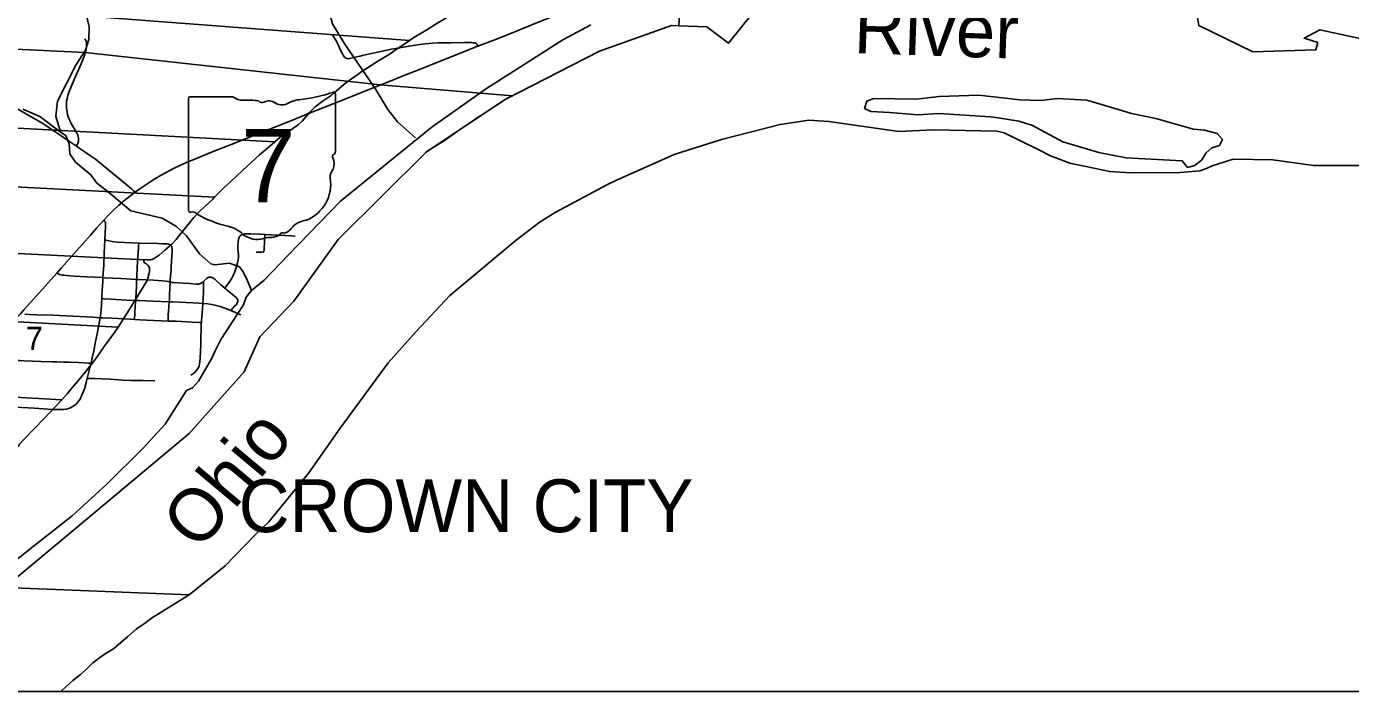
# Model space of a CAD drawing. Extents: x 0 to 34, y 0 to 22.
# Drawn here: x 27.11 to 29.485, y 14.1 to 15.294 of the extents above; entities that cross this region are included whole.
import ezdxf

# ---------------------------------------------------------------- set-up
doc = ezdxf.new("R2010")
doc.units = 0
for name, color, linetype in [('GM_X_City_Street', 7, 'Continuous'), ('GM_X_Corporation', 7, 'Continuous'), ('GM_X_Corporation_Text', 7, 'Continuous'), ('GM_X_County_Text', 7, 'Continuous'), ('GM_X_Major_River', 7, 'Continuous'), ('GM_X_Major_River_Text', 7, 'Continuous'), ('GM_X_Minor_River', 7, 'Continuous'), ('GM_X_Section', 7, 'Continuous'), ('GM_X_Section_Text', 7, 'Continuous'), ('GM_X_State_Location', 7, 'Continuous'), ('GM_X_State_Route', 7, 'Continuous'), ('GM_X_State_Shield', 7, 'Continuous'), ('GM_X_Township_Road', 7, 'Continuous'), ('SH_Cut_Line', 7, 'Continuous'), ('SH_Data', 7, 'Continuous')]:
    doc.layers.add(name, color=color, linetype=linetype)

msp = doc.modelspace()

# ---------------------------------------------------------------- linework, layer by layer
at = {"layer": 'GM_X_City_Street'}
for points in [[(27.0773, 14.6109), (27.1124, 14.609), (27.1242, 14.6084), (27.1478, 14.6069), (27.1583, 14.6064), (27.17, 14.6062), (27.1768, 14.6064), (27.181, 14.607), (27.1852, 14.6079), (27.1885, 14.6092), (27.1918, 14.6108), (27.1953, 14.6132), (27.1985, 14.6159), (27.201, 14.6186), (27.204, 14.6224), (27.2063, 14.626), (27.2085, 14.6304), (27.2114, 14.6372), (27.2134, 14.643), (27.2164, 14.6543), (27.2184, 14.6619), (27.2233, 14.6808), (27.2254, 14.6892), (27.2277, 14.6987), (27.2308, 14.7138), (27.2331, 14.7259), (27.2336, 14.7283), (27.2347, 14.7337), (27.2364, 14.7422), (27.239, 14.7549), (27.2412, 14.7671), (27.2417, 14.7707), (27.2424, 14.775), (27.2433, 14.7843), (27.2445, 14.8052), (27.2448, 14.8109), (27.2464, 14.8357), (27.2468, 14.8429), (27.2481, 14.8654), (27.2489, 14.8865), (27.25, 14.9104), (27.2515, 14.9348), (27.2516, 14.9409), (27.2511, 14.9422), (27.2503, 14.9434), (27.2475, 14.9453)], [(27.4942, 14.919), (27.4959, 14.9198), (27.4982, 14.9206), (27.5013, 14.9212), (27.5056, 14.9215), (27.5124, 14.9214), (27.528, 14.9207), (27.5372, 14.9203), (27.5479, 14.9198), (27.574, 14.9183), (27.5851, 14.9177), (27.5915, 14.9174)], [(27.5355, 14.889), (27.5359, 14.8939), (27.5367, 14.9081), (27.5371, 14.9173), (27.5372, 14.9203)], [(27.25, 14.9104), (27.2575, 14.9088), (27.2602, 14.9083), (27.2664, 14.9072), (27.2725, 14.9065), (27.2856, 14.906), (27.311, 14.9049), (27.3122, 14.9048), (27.3451, 14.904), (27.354, 14.9037), (27.3618, 14.9032), (27.3641, 14.9028), (27.3659, 14.9022), (27.367, 14.9016), (27.3679, 14.901), (27.3692, 14.8999), (27.3703, 14.8986)], [(27.3033, 14.7679), (27.3039, 14.7797), (27.3047, 14.7914), (27.3052, 14.7977), (27.3057, 14.8018), (27.306, 14.8066), (27.3065, 14.8157), (27.3068, 14.8268), (27.3072, 14.8396), (27.3074, 14.8441), (27.3083, 14.8609), (27.3096, 14.88), (27.3105, 14.8961), (27.3107, 14.8998), (27.311, 14.9049)], [(27.3636, 14.7649), (27.3638, 14.7687), (27.3639, 14.7718), (27.364, 14.7761), (27.3644, 14.7829), (27.365, 14.7909), (27.3656, 14.7994), (27.366, 14.8039), (27.3664, 14.8113), (27.367, 14.8243), (27.3673, 14.8347), (27.3675, 14.8391), (27.3689, 14.8571), (27.3694, 14.8626), (27.3703, 14.8805), (27.3708, 14.8898), (27.3708, 14.8939), (27.3706, 14.8971), (27.3703, 14.8986)], [(27.4653, 14.8238), (27.4705, 14.8305), (27.4752, 14.8371), (27.4781, 14.8418), (27.4806, 14.8468), (27.4832, 14.8532), (27.4857, 14.8608), (27.4881, 14.8692), (27.4893, 14.8747), (27.4898, 14.8796), (27.4898, 14.884), (27.4889, 14.8951), (27.4889, 14.8995), (27.4894, 14.9063), (27.4902, 14.9118), (27.4906, 14.9136), (27.4913, 14.9153), (27.4921, 14.9169), (27.4932, 14.9181), (27.4942, 14.919)], [(27.5214, 14.8886), (27.5278, 14.8887), (27.5324, 14.8888), (27.5355, 14.889)], [(27.1638, 14.8507), (27.1691, 14.8487), (27.1736, 14.8475), (27.1766, 14.847), (27.1815, 14.8465), (27.1951, 14.8456), (27.2174, 14.8444), (27.2468, 14.8429), (27.2503, 14.8427), (27.2788, 14.8414), (27.3072, 14.8396), (27.3104, 14.8394), (27.3377, 14.838), (27.3532, 14.8371), (27.3593, 14.8365), (27.3632, 14.8359), (27.3656, 14.8352), (27.3673, 14.8347), (27.3705, 14.8341), (27.3725, 14.8338), (27.3911, 14.8328), (27.4029, 14.832), (27.4142, 14.831), (27.4158, 14.8309), (27.417, 14.831), (27.4183, 14.8312), (27.4194, 14.8314), (27.4207, 14.8317), (27.4217, 14.8321), (27.4228, 14.8326), (27.4238, 14.8332), (27.4248, 14.8339), (27.4257, 14.8347), (27.4269, 14.836), (27.4325, 14.8412), (27.4346, 14.8426), (27.4358, 14.8432), (27.437, 14.8435), (27.4384, 14.8437), (27.4394, 14.8437), (27.4402, 14.8436), (27.4412, 14.8435), (27.4423, 14.8431), (27.444, 14.8424), (27.4453, 14.8416), (27.4462, 14.8409), (27.4481, 14.8394), (27.4495, 14.838), (27.4576, 14.8303), (27.4653, 14.8238), (27.4694, 14.8203), (27.4825, 14.8099), (27.4857, 14.8072), (27.4867, 14.8061), (27.4877, 14.8044), (27.4881, 14.8035)], [(27.4046, 14.6677), (27.408, 14.67), (27.4115, 14.6727), (27.4141, 14.6753), (27.4161, 14.6777), (27.4176, 14.6804), (27.4192, 14.6844), (27.4202, 14.688), (27.4209, 14.6923), (27.4214, 14.6991), (27.4217, 14.7103), (27.4222, 14.7233), (27.4223, 14.7326), (27.4227, 14.7525), (27.4231, 14.7599), (27.4234, 14.7623), (27.4238, 14.7667), (27.4243, 14.7723), (27.4259, 14.7952), (27.4259, 14.7962), (27.427, 14.8156), (27.4274, 14.8239), (27.4272, 14.8313), (27.4269, 14.836)], [(27.2445, 14.8052), (27.2491, 14.8049), (27.2609, 14.8041), (27.2702, 14.8035), (27.2893, 14.8025), (27.3057, 14.8018), (27.3123, 14.8016), (27.3365, 14.8006), (27.3656, 14.7994), (27.3724, 14.7991), (27.3842, 14.7985), (27.3959, 14.7979), (27.409, 14.7973), (27.4189, 14.7967), (27.4259, 14.7962), (27.4349, 14.7955), (27.4417, 14.7947), (27.4477, 14.7934), (27.4572, 14.7907), (27.4684, 14.787), (27.4764, 14.7839), (27.4845, 14.7805), (27.4943, 14.7763)], [(27.4764, 14.7839), (27.4794, 14.7873), (27.4836, 14.7919), (27.4861, 14.7948), (27.4876, 14.7969), (27.4882, 14.7986), (27.4886, 14.8), (27.4886, 14.8011), (27.4885, 14.8023), (27.4881, 14.8035)], [(27.1069, 14.7772), (27.1149, 14.7767), (27.1279, 14.7761), (27.1571, 14.7752), (27.193, 14.7737), (27.2172, 14.7726), (27.2289, 14.7718), (27.2417, 14.7707)], [(27.2417, 14.7707), (27.2463, 14.7705), (27.263, 14.7698), (27.2953, 14.7682), (27.3033, 14.7679), (27.3127, 14.7673), (27.3258, 14.7665), (27.3518, 14.7654), (27.3636, 14.7649), (27.3779, 14.7645), (27.3879, 14.764), (27.4071, 14.7628), (27.4202, 14.7624), (27.4234, 14.7623)], [(27.0272, 14.6976), (27.0383, 14.6967), (27.0572, 14.6959), (27.0742, 14.6949), (27.0823, 14.6944), (27.0934, 14.694), (27.0978, 14.6939), (27.1052, 14.6935), (27.1356, 14.6924), (27.1548, 14.6916), (27.1641, 14.6915), (27.1765, 14.6913), (27.187, 14.6911), (27.2031, 14.6903), (27.2205, 14.6894), (27.2254, 14.6892)], [(27.2184, 14.6619), (27.2323, 14.6616), (27.2441, 14.661), (27.2596, 14.6604), (27.2744, 14.6595), (27.2824, 14.659), (27.2976, 14.6584), (27.3192, 14.6579), (27.3397, 14.6577)]]:
    msp.add_lwpolyline(points, dxfattribs=at)
at = {"layer": 'GM_X_Corporation'}
msp.add_lwpolyline([(26.9519, 15.2596), (27.2149, 15.247), (27.7442, 15.1889), (27.9818, 15.1692), (27.9753, 15.166), (27.9674, 15.162), (27.9605, 15.1574), (27.944, 15.1463), (27.9311, 15.1378), (27.9164, 15.1281), (27.9019, 15.1184), (27.8907, 15.1109), (27.8595, 15.089), (27.83, 15.0701), (27.8265, 15.0679), (27.6689, 14.9115), (27.5892, 14.8006), (27.528, 14.7368), (27.5003, 14.6738), (27.4012, 14.5633), (27.1862, 14.3829), (27.0716, 14.2873)], dxfattribs=at)
at = {"layer": 'GM_X_County_Text'}
for points in [[(27.0716, 14.2873), (27.1862, 14.3829), (27.4012, 14.5633), (27.5003, 14.6738), (27.528, 14.7368), (27.5892, 14.8006), (27.6689, 14.9115), (27.8265, 15.0679), (27.967, 15.1616), (28.1376, 15.2493), (28.2671, 15.2953), (28.2799, 15.2948), (28.2867, 15.4004), (28.3527, 16.4269), (28.3944, 17.0528), (28.4159, 17.3358), (28.4427, 17.7695)], [(28.4427, 17.7695), (28.4159, 17.3358), (28.3944, 17.0528), (28.3527, 16.4269), (28.2867, 15.4004), (28.2799, 15.2948), (28.3301, 15.293), (28.3692, 15.2637), (28.4182, 15.3245), (28.4801, 15.3522), (28.6571, 15.3822), (28.9104, 15.3867), (29.0987, 15.3975), (29.1238, 15.3963), (29.3286, 15.3596), (29.3112, 15.3354), (29.211, 15.3094), (29.213, 15.295), (29.3097, 15.2479), (29.423, 15.2518), (29.4264, 15.2648), (29.4018, 15.2725), (29.4304, 15.2876), (29.5713, 15.2568)]]:
    msp.add_lwpolyline(points, dxfattribs=at)
at = {"layer": 'GM_X_Major_River'}
msp.add_line((27.0305, 14.2886), (27.4015, 14.2737), dxfattribs=at)
for points in [[(28.1223, 15.2965), (28.072, 15.2695), (27.9348, 15.1821), (27.8373, 15.1133), (27.7587, 15.0496), (27.6729, 14.9801), (27.5796, 14.8836), (27.5361, 14.8381), (27.5131, 14.8198), (27.5037, 14.8077), (27.4988, 14.794), (27.458, 14.7318), (27.4478, 14.7105), (27.4414, 14.6973), (27.418, 14.6567), (27.4074, 14.6453), (27.3964, 14.64), (27.3587, 14.58), (27.3183, 14.5359), (27.2544, 14.4725), (27.1913, 14.4152), (27.1214, 14.3605), (27.0305, 14.2886)], [(29.0923, 15.1371), (29.071, 15.1437), (29.0123, 15.1611), (28.959, 15.164), (28.9303, 15.1606), (28.8917, 15.1617), (28.8183, 15.1703), (28.7472, 15.1679), (28.7067, 15.1633), (28.63, 15.1644), (28.6171, 15.1594), (28.6133, 15.1465), (28.6243, 15.1409), (28.6587, 15.1394), (28.709, 15.1349), (28.7468, 15.1376), (28.8391, 15.1313), (28.8528, 15.1294), (28.8902, 15.1234), (28.9148, 15.1158), (28.9689, 15.0867), (29.0336, 15.0674), (29.0828, 15.058)], [(29.0828, 15.058), (29.1833, 15.0526), (29.1928, 15.0405), (29.2057, 15.0443), (29.2185, 15.0542), (29.2265, 15.0667), (29.2367, 15.0758), (29.25, 15.08), (29.2556, 15.0907), (29.2461, 15.1013), (29.2234, 15.1077), (29.2033, 15.1092), (29.1358, 15.1284), (29.0923, 15.1371)], [(27.4015, 14.2737), (27.466, 14.3257), (27.52, 14.3815), (27.5446, 14.4043), (27.6159, 14.4924), (27.6722, 14.5728), (27.7583, 14.6901), (27.8086, 14.7463), (27.8694, 14.8108), (27.9884, 14.9103), (28.0311, 14.943), (28.0583, 14.9597), (28.1521, 15.0102), (28.1672, 15.0171), (28.2715, 15.0638), (28.3566, 15.0905), (28.4617, 15.1179), (28.5135, 15.1256), (28.5494, 15.1233), (28.675, 15.1049), (28.7363, 15.108), (28.8505, 15.1055), (28.8637, 15.1029), (28.925, 15.073), (28.947, 15.0613), (28.9818, 15.048), (29.0533, 15.033), (29.0911, 15.0311)], [(29.0911, 15.0311), (29.1795, 15.0317), (29.2151, 15.0345), (29.2269, 15.0386), (29.2371, 15.0436), (29.2746, 15.0554), (29.3459, 15.0544), (29.419, 15.0438), (29.5115, 15.044)], [(27.1711, 14.1), (27.1805, 14.109), (27.193, 14.1197), (27.2058, 14.13), (27.2171, 14.1399), (27.2288, 14.1517), (27.2408, 14.1605), (27.251, 14.1674), (27.2657, 14.1769), (27.2789, 14.188), (27.291, 14.1979), (27.3064, 14.212), (27.323, 14.2235), (27.3336, 14.2319), (27.4015, 14.2737)]]:
    msp.add_lwpolyline(points, dxfattribs=at)
at = {"layer": 'GM_X_Minor_River'}
for points in [[(27.1708, 15.1045), (27.1625, 15.1324), (27.1653, 15.1597), (27.1982, 15.2243), (27.2153, 15.2508), (27.2215, 15.2699), (27.2222, 15.2931), (27.2141, 15.326), (27.2073, 15.3604), (27.1796, 15.4095), (27.1705, 15.4333), (27.1577, 15.496), (27.1332, 15.5484), (27.123, 15.5719), (27.1185, 15.6005)], [(27.8078, 15.0936), (27.775, 15.1224), (27.7579, 15.1446), (27.7366, 15.1806), (27.6794, 15.2637), (27.6589, 15.2981), (27.6545, 15.3138), (27.5904, 15.4309), (27.545, 15.4779), (27.496, 15.5072), (27.4775, 15.5222), (27.4551, 15.556)], [(27.5131, 14.8198), (27.5045, 14.8413), (27.4973, 14.8548), (27.4915, 14.8619), (27.4739, 14.8685), (27.4474, 14.8655), (27.4406, 14.8673), (27.42, 14.8854), (27.3964, 14.9177), (27.3788, 14.9346), (27.3528, 14.9494), (27.2969, 14.9626), (27.2534, 14.9993), (27.236, 15.0124), (27.2251, 15.0272), (27.1978, 15.0501), (27.1873, 15.0652), (27.1864, 15.0831), (27.18, 15.0977), (27.1726, 15.1029), (27.1334, 15.1319), (27.1028, 15.1454)]]:
    msp.add_lwpolyline(points, dxfattribs=at)
at = {"layer": 'GM_X_Section'}
msp.add_lwpolyline([(27.1082, 16.21), (27.1198, 16.4014), (27.6098, 16.3785), (28.1612, 16.354), (28.1022, 15.4021), (28.0942, 15.3994), (28.073, 15.3933), (28.0541, 15.3891), (28.0393, 15.3864), (28.0147, 15.3799), (27.9901, 15.3708), (27.9704, 15.362), (27.9454, 15.3502), (27.9269, 15.3415), (27.9046, 15.3316), (27.8826, 15.3209), (27.8697, 15.3133), (27.8576, 15.3061), (27.8429, 15.297), (27.8281, 15.2875), (27.8077, 15.2753), (27.7994, 15.27), (27.7971, 15.2681), (27.0537, 15.3245)], dxfattribs=at)
for points in [[(27.0537, 15.3245), (27.7971, 15.2681), (27.7884, 15.2624), (27.7785, 15.2559), (27.771, 15.251), (27.7619, 15.2445), (27.743, 15.2331), (27.7146, 15.2152), (27.6987, 15.2038), (27.6828, 15.1924), (27.6624, 15.1753), (27.656, 15.1697), (27.6401, 15.159), (27.6276, 15.1491), (27.6174, 15.1393), (27.6042, 15.1237), (27.597, 15.1172), (27.5777, 15.1036), (27.5644, 15.0941), (27.5553, 15.0864), (27.0368, 15.114)], [(27.0368, 15.114), (27.5553, 15.0864), (27.5463, 15.0789), (27.5274, 15.0629), (27.4979, 15.0356), (27.4752, 15.0143), (27.4642, 15.0048), (27.447, 14.9872), (27.0298, 15.0085)], [(27.447, 14.9872), (27.4438, 14.9839), (27.4294, 14.9703), (27.4192, 14.9608), (27.4098, 14.9505), (27.3965, 14.9346), (27.3799, 14.9137), (27.378, 14.9114), (27.3701, 14.9027), (27.3576, 14.892), (27.3478, 14.8833), (27.3387, 14.8769), (27.3345, 14.8753), (27.3315, 14.8746), (27.3262, 14.8749), (27.3237, 14.8752), (27.3209, 14.8747), (27.022, 14.8897), (27.0298, 15.0085)], [(27.022, 14.8897), (27.3209, 14.8747), (27.3201, 14.872), (27.3206, 14.8702), (27.322, 14.8685), (27.3251, 14.8673), (27.3277, 14.8647), (27.33, 14.8609), (27.3304, 14.8586), (27.3304, 14.853), (27.3274, 14.8416), (27.3263, 14.8374), (27.3149, 14.8192), (27.2908, 14.7801), (27.2738, 14.754), (27.0139, 14.7675)], [(27.2738, 14.754), (27.2674, 14.7441), (27.2492, 14.719), (27.2345, 14.6982), (27.2179, 14.6765), (27.2043, 14.6602), (27.1873, 14.6405), (27.1831, 14.6348), (27.1729, 14.6236), (27.005, 14.633), (27.0139, 14.7675)], [(27.005, 14.633), (27.1729, 14.6236), (27.1404, 14.5896), (27.1241, 14.5721), (27.1041, 14.552), (27.0973, 14.544), (27.0954, 14.5406), (27.0791, 14.5254), (27.0708, 14.5178), (27.0621, 14.5102), (27.0545, 14.5034), (27.0428, 14.4943), (27.0409, 14.4927), (26.9958, 14.4952)]]:
    msp.add_lwpolyline(points, close=True, dxfattribs=at)
at = {"layer": 'GM_X_State_Route'}
for points in [[(27.7444, 15.1883), (27.7503, 15.1906), (27.7883, 15.2059), (27.8178, 15.2176), (27.8385, 15.2259), (27.861, 15.2348), (27.9194, 15.2582), (27.9513, 15.2704), (27.983, 15.283), (28.0236, 15.2993), (28.0779, 15.321), (28.1349, 15.3435), (28.1831, 15.3628), (28.219, 15.3769), (28.2361, 15.383), (28.2523, 15.3887), (28.2657, 15.3931)], [(27.3044, 14.9962), (27.3111, 15.0011), (27.3271, 15.0119), (27.337, 15.0182), (27.3552, 15.0289), (27.376, 15.0399), (27.3838, 15.0437), (27.3992, 15.0504), (27.4118, 15.0556), (27.4417, 15.0678), (27.474, 15.0806), (27.5024, 15.0918), (27.5387, 15.1065), (27.5808, 15.1232), (27.6183, 15.1383), (27.6432, 15.148), (27.6766, 15.1614), (27.7258, 15.1809), (27.7444, 15.1883)], [(27.3044, 14.9962), (27.301, 14.9993), (27.2978, 15.0022), (27.2707, 15.025), (27.2403, 15.0497), (27.2332, 15.0552), (27.2264, 15.0602), (27.2133, 15.0692), (27.1991, 15.079), (27.1813, 15.091), (27.1478, 15.1134), (27.137, 15.1204), (27.1336, 15.1226), (27.1305, 15.1245), (27.0785, 15.1539)], [(27.2244, 14.9193), (27.235, 14.9314), (27.2475, 14.9453), (27.2559, 14.9542), (27.2652, 14.9634), (27.2748, 14.9721), (27.2866, 14.9822), (27.3044, 14.9962)], [(27.023, 14.6929), (27.0272, 14.6976), (27.0343, 14.7058), (27.0625, 14.7373), (27.075, 14.7519), (27.0854, 14.7634), (27.0955, 14.7744), (27.0986, 14.7778), (27.1055, 14.7855), (27.1222, 14.8039), (27.1638, 14.8507), (27.1725, 14.8605), (27.1994, 14.8907), (27.2104, 14.9034), (27.2244, 14.9193)]]:
    msp.add_lwpolyline(points, dxfattribs=at)
at = {"layer": 'GM_X_State_Shield'}
for p, q in [((27.4001, 15.164), (27.4001, 14.9639)), ((27.4799, 15.1675), (27.4027, 15.1675)), ((27.6638, 15.0677), (27.6638, 15.1724)), ((27.6638, 15.0678), (27.6638, 15.0677))]:
    msp.add_line(p, q, dxfattribs=at)
for centre, radius, start, end in [((27.4031, 15.1644), 0.00305, 98.1301, 188.1301), ((27.4983, 15.1907), 0.0296, 231.6195, 271.1119), ((27.5081, 15.0551), 0.1064, 80.4867, 94.9883), ((27.5323, 15.1655), 0.00855, 219.7921, 297.1024), ((27.5448, 15.1423), 0.0178, 54.4667, 119.1411), ((27.6055, 15.1063), 0.0563, 97.3462, 120.7689), ((27.5699, 15.4403), 0.2796, 275.8445, 288.9065), ((27.6609, 15.1728), 0.00294, 351.8621, 97.738), ((27.5678, 15.1741), 0.0214, 233.8562, 294.8282), ((27.6631, 15.06), 0.00454, 107.944, 210.337), ((27.6606, 15.0673), 0.00314, 289.6038, 7.7341), ((27.6342, 15.0468), 0.0273, 340.033, 23.6496), ((27.5855, 15.0106), 0.0699, 292.3089, 8.9858), ((27.6743, 15.0239), 0.0198, 136.8065, 186.9296), ((27.4032, 14.9635), 0.00308, 171.9584, 258.3066), ((27.4036, 14.9839), 0.0235, 267.339, 280.6039), ((27.4084, 14.9523), 0.00848, 29.7484, 93.2717), ((27.5155, 15.1321), 0.2019, 240.4129, 257.1985), ((27.615, 14.9077), 0.0383, 94.4031, 142.5768), ((27.4553, 14.874), 0.0632, 47.1842, 75.836), ((27.5236, 14.9514), 0.0401, 230.7004, 286.2918), ((27.5497, 14.9364), 0.0214, 268.777, 315.5493), ((27.569, 14.917), 0.00601, 65.7517, 132.6484), ((27.5665, 14.9445), 0.0226, 282.8732, 323.2771), ((27.5468, 14.8822), 0.0329, 85.6951, 111.2099)]:
    msp.add_arc(centre, radius, start, end, dxfattribs=at)
at = {"layer": 'GM_X_Township_Road'}
for points in [[(27.6593, 15.2771), (27.6644, 15.2692), (27.6668, 15.2649), (27.671, 15.2552), (27.6741, 15.2485), (27.6765, 15.2442), (27.6777, 15.2421), (27.6787, 15.2405), (27.6803, 15.2386), (27.6816, 15.2374), (27.6832, 15.2364), (27.6849, 15.2358), (27.6867, 15.2356), (27.6892, 15.2359), (27.6994, 15.2383), (27.7084, 15.2405), (27.7125, 15.2415), (27.717, 15.2424), (27.7255, 15.2442), (27.7451, 15.2484), (27.7648, 15.2527), (27.7685, 15.2534)], [(27.2151, 15.2465), (27.2157, 15.2484), (27.2161, 15.2503), (27.2166, 15.2522), (27.2168, 15.254), (27.2171, 15.2563), (27.2173, 15.2585), (27.2174, 15.2605), (27.2175, 15.2623), (27.2174, 15.264), (27.2171, 15.2655), (27.2168, 15.267), (27.2163, 15.2682), (27.2157, 15.2693), (27.2144, 15.2715)], [(27.7685, 15.2534), (27.7758, 15.2548), (27.796, 15.2583), (27.815, 15.2614), (27.8193, 15.2619), (27.8255, 15.2626), (27.8379, 15.2636), (27.8484, 15.2639), (27.8714, 15.2643), (27.8956, 15.2647), (27.9037, 15.2648), (27.9087, 15.2645), (27.9117, 15.2643), (27.9141, 15.2639), (27.9158, 15.2633), (27.917, 15.2624), (27.918, 15.2609), (27.9194, 15.2582)], [(27.1991, 15.079), (27.2015, 15.0842), (27.2022, 15.0862), (27.2027, 15.088), (27.203, 15.0898), (27.2031, 15.0918), (27.2029, 15.0939), (27.2024, 15.0959), (27.2018, 15.0979), (27.2009, 15.1002), (27.1997, 15.1027), (27.19, 15.1193), (27.1878, 15.1233), (27.1859, 15.1275), (27.1844, 15.1316), (27.1832, 15.1357), (27.1823, 15.14), (27.1818, 15.1438), (27.1815, 15.147), (27.1812, 15.1507), (27.1812, 15.1536), (27.1813, 15.1564), (27.1816, 15.1597), (27.1823, 15.1635), (27.183, 15.1666), (27.1839, 15.1703), (27.1849, 15.1735), (27.186, 15.1768), (27.1949, 15.1986), (27.2052, 15.2211), (27.2076, 15.2266), (27.2101, 15.2327), (27.2122, 15.2384), (27.2151, 15.2465)]]:
    msp.add_lwpolyline(points, dxfattribs=at)
at = {"layer": 'SH_Cut_Line'}
for points in [[(28.2799, 15.2948), (28.3301, 15.293), (28.3692, 15.2637), (28.4182, 15.3245)], [(27.0716, 14.2873), (27.1862, 14.3829), (27.4012, 14.5633), (27.5003, 14.6738), (27.528, 14.7368), (27.5892, 14.8006), (27.6689, 14.9115), (27.8265, 15.0679), (27.967, 15.1616), (28.1376, 15.2493), (28.2671, 15.2953)], [(29.213, 15.295), (29.3097, 15.2479), (29.423, 15.2518), (29.4264, 15.2648), (29.4018, 15.2725), (29.4304, 15.2876), (29.5713, 15.2568)]]:
    msp.add_lwpolyline(points, dxfattribs=at)
at = {"layer": 'SH_Data'}
msp.add_lwpolyline([(23.8372, 20.9), (30.6372, 20.9), (30.6372, 14.1), (23.8372, 14.1)], close=True, dxfattribs=at)

# ---------------------------------------------------------------- texts
at = {"layer": 'GM_X_Corporation_Text'}
msp.add_text('CROWN CITY', height=0.0947, rotation=0, dxfattribs=at).set_placement((27.4902, 14.386))
at = {"layer": 'GM_X_Major_River_Text'}
for s, rotation, p in [('River', 357.9954, (28.5931, 15.246)), ('Ohio', 50.0025, (27.4189, 14.3498))]:
    msp.add_text(s, height=0.0947, rotation=rotation, dxfattribs=at).set_placement(p)
at = {"layer": 'GM_X_Section_Text'}
msp.add_text('7', height=0.0419, rotation=0, dxfattribs=at).set_placement((27.108, 14.7127))
at = {"layer": 'GM_X_State_Location'}
for s in ['s', 'r']:
    msp.add_text(s, height=0.000189, dxfattribs=at).set_placement((27.529, 15.0506))
msp.add_text('7', height=0.000189, rotation=0, dxfattribs=at).set_placement((27.5005, 15.0369))
at = {"layer": 'GM_X_State_Shield'}
msp.add_text('7', height=0.1318, dxfattribs=at).set_placement((27.4942, 14.978))

doc.saveas('drawing.dxf')
